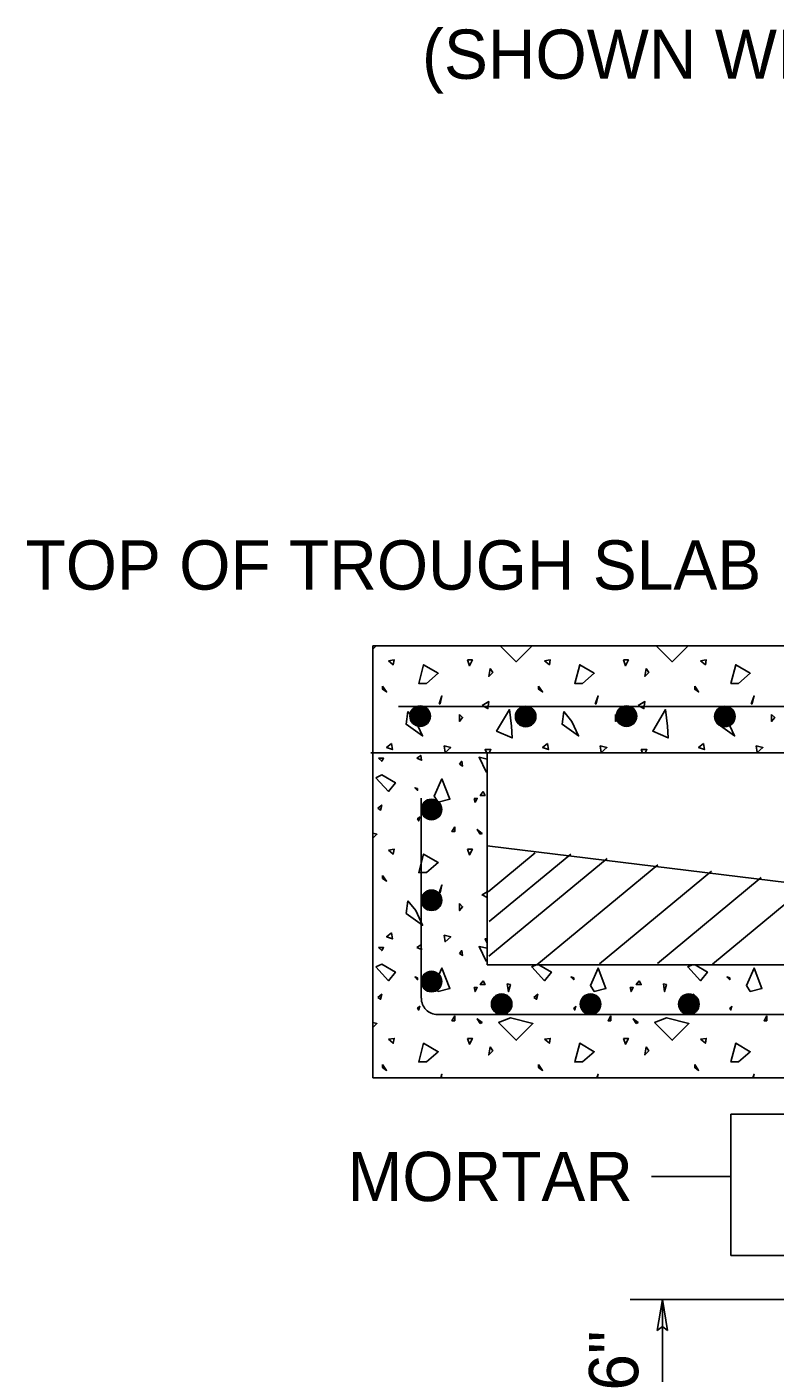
# Model space of a CAD drawing. Extents: x 5.8 to 18, y -5.2 to 5.4.
# Drawn here: x 5.844 to 6.755, y -0.7 to 0.939 of the extents above; entities that cross this region are included whole.
import ezdxf

# ---------------------------------------------------------------- set-up
doc = ezdxf.new("R2010")
doc.units = 0
for name, color, linetype in [('DETL-DIMS', 7, 'Continuous'), ('DETL-LINE', 7, 'Continuous'), ('DETL-NOTE', 7, 'Continuous'), ('DETL-PATT', 7, 'Continuous')]:
    doc.layers.add(name, color=color, linetype=linetype)

msp = doc.modelspace()

# ---------------------------------------------------------------- linework, layer by layer
at = {"layer": 'DETL-DIMS'}
for p, q in [((6.7009, -0.4604), (6.7009, -0.3844)), ((6.7009, -0.3844), (7.037, -0.3844)), ((6.6043, -0.4604), (6.7009, -0.4604)), ((6.7009, -0.4604), (6.7009, -0.5566)), ((6.7009, -0.5566), (7.0309, -0.5566)), ((6.8399, -0.6101), (6.5782, -0.6101)), ((6.6112, -0.6478), (6.6175, -0.6101)), ((6.6175, -0.7393), (6.6175, -0.6101)), ((6.6237, -0.6478), (6.6175, -0.6101)), ((6.6112, -0.6478), (6.6175, -0.6431)), ((6.6237, -0.6478), (6.6175, -0.6431))]:
    msp.add_line(p, q, dxfattribs=at)
at = {"layer": 'DETL-LINE'}
for p, q in [((6.2649, -0.3403), (6.2649, 0.1856)), ((6.2649, 0.1856), (8.658, 0.1856)), ((6.296, 0.112), (7.1107, 0.112)), ((6.2624, 0.0554), (8.658, 0.0554)), ((6.404, -0.2028), (6.404, 0.0554)), ((6.3238, -0.2434), (6.3238, 0.0002)), ((7.1567, -0.1499), (6.404, -0.0577)), ((6.404, -0.2028), (8.5262, -0.2028)), ((6.3435, -0.2631), (7.0378, -0.2631)), ((6.2649, -0.3403), (7.037, -0.3403))]:
    msp.add_line(p, q, dxfattribs=at)
for centre, radius in [((6.3224, 0.1001), 0.0125), ((6.3223, 0.1002), 0.0116), ((6.3212, 0.1002), 0.0101), ((6.3224, 0.0999), 0.0112), ((6.3228, 0.0993), 0.011), ((6.3227, 0.0997), 0.0102), ((6.3216, 0.1007), 0.00834), ((6.323, 0.0997), 0.00969), ((6.3231, 0.0994), 0.00918), ((6.3214, 0.0997), 0.00724), ((6.3232, 0.0993), 0.00876), ((6.3231, 0.0991), 0.00835), ((6.3208, 0.0993), 0.00578), ((6.3233, 0.0991), 0.00814), ((6.3231, 0.0992), 0.00786), ((6.3235, 0.099), 0.00751), ((6.3235, 0.0991), 0.00704), ((6.3236, 0.0992), 0.00655), ((6.3217, 0.0995), 0.00467), ((6.3236, 0.0993), 0.006), ((6.3237, 0.0992), 0.00565), ((6.3237, 0.0991), 0.0051), ((6.3239, 0.0987), 0.00488), ((6.324, 0.0986), 0.00445), ((6.324, 0.0988), 0.0039), ((6.3242, 0.0989), 0.00377), ((6.3242, 0.0985), 0.00347), ((6.3243, 0.0988), 0.00333), ((6.3244, 0.0987), 0.00285), ((6.3242, 0.0989), 0.00238), ((6.3245, 0.0986), 0.00212), ((6.3245, 0.0986), 0.00175), ((6.3247, 0.0986), 0.00133), ((6.3247, 0.0987), 0.00118), ((6.3251, 0.0986), 0.00148), ((6.3246, 0.0987), 0.000769), ((6.3245, 0.0987), 0.000362), ((6.3248, 0.0987), 0.00023), ((6.451, 0.0996), 0.0125), ((6.4509, 0.0997), 0.0116), ((6.4498, 0.0997), 0.0101), ((6.451, 0.0994), 0.0112), ((6.4513, 0.0988), 0.011), ((6.4513, 0.0992), 0.0102), ((6.4502, 0.1002), 0.00834), ((6.4516, 0.0992), 0.00969), ((6.4516, 0.0989), 0.00918), ((6.45, 0.0992), 0.00724), ((6.4518, 0.0988), 0.00876), ((6.4516, 0.0986), 0.00835), ((6.4493, 0.0988), 0.00578), ((6.4519, 0.0986), 0.00814), ((6.4517, 0.0987), 0.00786), ((6.4521, 0.0985), 0.00751), ((6.4521, 0.0986), 0.00704), ((6.4522, 0.0987), 0.00655), ((6.4503, 0.099), 0.00467), ((6.4522, 0.0988), 0.006), ((6.4523, 0.0987), 0.00565), ((6.4523, 0.0986), 0.0051), ((6.4525, 0.0982), 0.00488), ((6.4526, 0.0981), 0.00445), ((6.4526, 0.0983), 0.0039), ((6.4528, 0.0984), 0.00377), ((6.4528, 0.098), 0.00347), ((6.4529, 0.0983), 0.00333), ((6.453, 0.0982), 0.00285), ((6.4528, 0.0984), 0.00238), ((6.453, 0.0981), 0.00212), ((6.4531, 0.0981), 0.00175), ((6.4532, 0.0981), 0.00133), ((6.4532, 0.0982), 0.00118), ((6.4537, 0.0981), 0.00148), ((6.4532, 0.0982), 0.000769), ((6.4531, 0.0982), 0.000362), ((6.4534, 0.0982), 0.00023), ((6.5737, 0.1001), 0.0125), ((6.5736, 0.1002), 0.0116), ((6.5725, 0.1002), 0.0101), ((6.5738, 0.0999), 0.0112), ((6.5741, 0.0993), 0.011), ((6.574, 0.0997), 0.0102), ((6.5743, 0.0997), 0.00969), ((6.5729, 0.1007), 0.00834), ((6.5744, 0.0994), 0.00918), ((6.5727, 0.0997), 0.00724), ((6.5745, 0.0993), 0.00876), ((6.5744, 0.0991), 0.00835), ((6.5721, 0.0993), 0.00578), ((6.5746, 0.0991), 0.00814), ((6.5745, 0.0992), 0.00786), ((6.5748, 0.099), 0.00751), ((6.5749, 0.0991), 0.00704), ((6.5749, 0.0992), 0.00655), ((6.5731, 0.0995), 0.00467), ((6.5749, 0.0993), 0.006), ((6.575, 0.0992), 0.00565), ((6.575, 0.0991), 0.0051), ((6.5752, 0.0987), 0.00488), ((6.5754, 0.0986), 0.00445), ((6.5754, 0.0988), 0.0039), ((6.5755, 0.0989), 0.00377), ((6.5755, 0.0985), 0.00347), ((6.5756, 0.0988), 0.00333), ((6.5757, 0.0987), 0.00285), ((6.5755, 0.0989), 0.00238), ((6.5758, 0.0986), 0.00212), ((6.5759, 0.0986), 0.00175), ((6.576, 0.0986), 0.00133), ((6.576, 0.0987), 0.00118), ((6.5764, 0.0986), 0.00148), ((6.576, 0.0987), 0.000769), ((6.5758, 0.0987), 0.000362), ((6.5761, 0.0987), 0.00023), ((6.6935, 0.0996), 0.0125), ((6.6934, 0.0997), 0.0116), ((6.6923, 0.0997), 0.0101), ((6.6936, 0.0994), 0.0112), ((6.6939, 0.0988), 0.011), ((6.6938, 0.0992), 0.0102), ((6.6941, 0.0992), 0.00969), ((6.6927, 0.1002), 0.00834), ((6.6942, 0.0989), 0.00918), ((6.6925, 0.0992), 0.00724), ((6.6943, 0.0988), 0.00876), ((6.6942, 0.0986), 0.00835), ((6.6919, 0.0988), 0.00578), ((6.6944, 0.0986), 0.00814), ((6.6942, 0.0987), 0.00786), ((6.6946, 0.0985), 0.00751), ((6.6947, 0.0986), 0.00704), ((6.6947, 0.0987), 0.00655), ((6.6929, 0.099), 0.00467), ((6.6947, 0.0988), 0.006), ((6.6948, 0.0987), 0.00565), ((6.6948, 0.0986), 0.0051), ((6.695, 0.0982), 0.00488), ((6.6951, 0.0981), 0.00445), ((6.6951, 0.0983), 0.0039), ((6.6953, 0.0984), 0.00377), ((6.6953, 0.098), 0.00347), ((6.6954, 0.0983), 0.00333), ((6.6955, 0.0982), 0.00285), ((6.6953, 0.0984), 0.00238), ((6.6956, 0.0981), 0.00212), ((6.6957, 0.0981), 0.00175), ((6.6958, 0.0981), 0.00133), ((6.6958, 0.0982), 0.00118), ((6.6962, 0.0981), 0.00148), ((6.6958, 0.0982), 0.000769), ((6.6956, 0.0982), 0.000362), ((6.6959, 0.0982), 0.00023), ((6.3363, -0.0135), 0.0125), ((6.3362, -0.0134), 0.0116), ((6.3351, -0.0134), 0.0101), ((6.3363, -0.0136), 0.0112), ((6.3367, -0.0142), 0.011), ((6.3366, -0.0138), 0.0102), ((6.3369, -0.0138), 0.00969), ((6.3355, -0.0129), 0.00834), ((6.337, -0.0141), 0.00918), ((6.3353, -0.0138), 0.00724), ((6.3371, -0.0143), 0.00876), ((6.337, -0.0145), 0.00835), ((6.3347, -0.0143), 0.00578), ((6.3372, -0.0145), 0.00814), ((6.337, -0.0143), 0.00786), ((6.3374, -0.0145), 0.00751), ((6.3375, -0.0144), 0.00704), ((6.3375, -0.0143), 0.00655), ((6.3356, -0.014), 0.00467), ((6.3375, -0.0142), 0.006), ((6.3376, -0.0143), 0.00565), ((6.3376, -0.0144), 0.0051), ((6.3378, -0.0148), 0.00488), ((6.3379, -0.0149), 0.00445), ((6.3379, -0.0148), 0.0039), ((6.3381, -0.0147), 0.00377), ((6.3381, -0.015), 0.00347), ((6.3382, -0.0147), 0.00333), ((6.3383, -0.0148), 0.00285), ((6.3381, -0.0146), 0.00238), ((6.3384, -0.0149), 0.00212), ((6.3384, -0.0149), 0.00175), ((6.3386, -0.015), 0.00133), ((6.3386, -0.0148), 0.00118), ((6.339, -0.0149), 0.00148), ((6.3386, -0.0148), 0.000769), ((6.3384, -0.0148), 0.000362), ((6.3387, -0.0148), 0.00023), ((6.3363, -0.1241), 0.0125), ((6.3362, -0.124), 0.0116), ((6.3351, -0.124), 0.0101), ((6.3363, -0.1243), 0.0112), ((6.3367, -0.1248), 0.011), ((6.3366, -0.1244), 0.0102), ((6.3369, -0.1245), 0.00969), ((6.3355, -0.1235), 0.00834), ((6.337, -0.1248), 0.00918), ((6.3353, -0.1245), 0.00724), ((6.3371, -0.1249), 0.00876), ((6.337, -0.1251), 0.00835), ((6.3347, -0.1249), 0.00578), ((6.3372, -0.1251), 0.00814), ((6.337, -0.125), 0.00786), ((6.3374, -0.1252), 0.00751), ((6.3375, -0.1251), 0.00704), ((6.3375, -0.125), 0.00655), ((6.3356, -0.1246), 0.00467), ((6.3375, -0.1248), 0.006), ((6.3376, -0.125), 0.00565), ((6.3376, -0.1251), 0.0051), ((6.3378, -0.1255), 0.00488), ((6.3379, -0.1255), 0.00445), ((6.3379, -0.1254), 0.0039), ((6.3381, -0.1253), 0.00377), ((6.3381, -0.1257), 0.00347), ((6.3382, -0.1254), 0.00333), ((6.3383, -0.1255), 0.00285), ((6.3381, -0.1253), 0.00238), ((6.3384, -0.1256), 0.00212), ((6.3384, -0.1255), 0.00175), ((6.3386, -0.1256), 0.00133), ((6.3386, -0.1255), 0.00118), ((6.339, -0.1255), 0.00148), ((6.3386, -0.1255), 0.000769), ((6.3384, -0.1255), 0.000362), ((6.3387, -0.1255), 0.00023), ((6.3363, -0.2231), 0.0125), ((6.3362, -0.223), 0.0116), ((6.3351, -0.223), 0.0101), ((6.3363, -0.2233), 0.0112), ((6.3367, -0.2238), 0.011), ((6.3366, -0.2234), 0.0102), ((6.3369, -0.2235), 0.00969), ((6.3355, -0.2225), 0.00834), ((6.337, -0.2238), 0.00918), ((6.3353, -0.2235), 0.00724), ((6.3371, -0.2239), 0.00876), ((6.337, -0.2241), 0.00835), ((6.3347, -0.2239), 0.00578), ((6.3372, -0.2241), 0.00814), ((6.337, -0.224), 0.00786), ((6.3374, -0.2242), 0.00751), ((6.3375, -0.224), 0.00704), ((6.3375, -0.224), 0.00655), ((6.3356, -0.2236), 0.00467), ((6.3375, -0.2238), 0.006), ((6.3376, -0.224), 0.00565), ((6.3376, -0.224), 0.0051), ((6.3378, -0.2245), 0.00488), ((6.3379, -0.2245), 0.00445), ((6.3379, -0.2244), 0.0039), ((6.3381, -0.2243), 0.00377), ((6.3381, -0.2247), 0.00347), ((6.3382, -0.2244), 0.00333), ((6.3383, -0.2245), 0.00285), ((6.3381, -0.2243), 0.00238), ((6.3384, -0.2245), 0.00212), ((6.3384, -0.2245), 0.00175), ((6.3386, -0.2246), 0.00133), ((6.3386, -0.2245), 0.00118), ((6.339, -0.2245), 0.00148), ((6.3386, -0.2245), 0.000769), ((6.3384, -0.2245), 0.000362), ((6.3387, -0.2245), 0.00023), ((6.4217, -0.2506), 0.0125), ((6.4216, -0.2505), 0.0116), ((6.4205, -0.2505), 0.0101), ((6.4218, -0.2508), 0.0112), ((6.4221, -0.2514), 0.011), ((6.422, -0.251), 0.0102), ((6.4223, -0.251), 0.00969), ((6.4209, -0.25), 0.00834), ((6.4224, -0.2513), 0.00918), ((6.4207, -0.251), 0.00724), ((6.4225, -0.2514), 0.00876), ((6.4224, -0.2516), 0.00835), ((6.4201, -0.2514), 0.00578), ((6.4226, -0.2516), 0.00814), ((6.4224, -0.2515), 0.00786), ((6.4228, -0.2517), 0.00751), ((6.4229, -0.2516), 0.00704), ((6.4229, -0.2515), 0.00655), ((6.4229, -0.2514), 0.006), ((6.5299, -0.2506), 0.0125), ((6.5298, -0.2505), 0.0116), ((6.5287, -0.2505), 0.0101), ((6.5299, -0.2508), 0.0112), ((6.5302, -0.2514), 0.011), ((6.5302, -0.251), 0.0102), ((6.5291, -0.25), 0.00834), ((6.5305, -0.251), 0.00969), ((6.5305, -0.2513), 0.00918), ((6.5289, -0.251), 0.00724), ((6.5307, -0.2514), 0.00876), ((6.5305, -0.2516), 0.00835), ((6.5282, -0.2514), 0.00578), ((6.5308, -0.2516), 0.00814), ((6.5306, -0.2515), 0.00786), ((6.531, -0.2517), 0.00751), ((6.531, -0.2516), 0.00704), ((6.5311, -0.2515), 0.00655), ((6.5311, -0.2514), 0.006), ((6.6497, -0.2506), 0.0125), ((6.6496, -0.2505), 0.0116), ((6.6485, -0.2505), 0.0101), ((6.6497, -0.2508), 0.0112), ((6.6501, -0.2514), 0.011), ((6.65, -0.251), 0.0102), ((6.6489, -0.25), 0.00834), ((6.6503, -0.251), 0.00969), ((6.6503, -0.2513), 0.00918), ((6.6487, -0.251), 0.00724), ((6.6505, -0.2514), 0.00876), ((6.6503, -0.2516), 0.00835), ((6.6481, -0.2514), 0.00578), ((6.6506, -0.2516), 0.00814), ((6.6504, -0.2515), 0.00786), ((6.6508, -0.2517), 0.00751), ((6.6508, -0.2516), 0.00704), ((6.6509, -0.2515), 0.00655), ((6.6509, -0.2514), 0.006), ((6.4211, -0.2512), 0.00467), ((6.423, -0.2515), 0.00565), ((6.423, -0.2516), 0.0051), ((6.4232, -0.252), 0.00488), ((6.4233, -0.2521), 0.00445), ((6.4233, -0.2519), 0.0039), ((6.4235, -0.2518), 0.00377), ((6.4235, -0.2522), 0.00347), ((6.4236, -0.2519), 0.00333), ((6.4237, -0.252), 0.00285), ((6.4235, -0.2518), 0.00238), ((6.4238, -0.2521), 0.00212), ((6.4239, -0.2521), 0.00175), ((6.424, -0.2521), 0.00133), ((6.424, -0.252), 0.00118), ((6.4244, -0.2521), 0.00148), ((6.424, -0.252), 0.000769), ((6.4238, -0.252), 0.000362), ((6.4241, -0.252), 0.00023), ((6.5292, -0.2512), 0.00467), ((6.5312, -0.2515), 0.00565), ((6.5312, -0.2516), 0.0051), ((6.5314, -0.252), 0.00488), ((6.5315, -0.2521), 0.00445), ((6.5315, -0.2519), 0.0039), ((6.5317, -0.2518), 0.00377), ((6.5317, -0.2522), 0.00347), ((6.5318, -0.2519), 0.00333), ((6.5319, -0.252), 0.00285), ((6.5317, -0.2518), 0.00238), ((6.5319, -0.2521), 0.00212), ((6.532, -0.2521), 0.00175), ((6.5321, -0.2521), 0.00133), ((6.5321, -0.252), 0.00118), ((6.5326, -0.2521), 0.00148), ((6.5321, -0.252), 0.000769), ((6.532, -0.252), 0.000362), ((6.5323, -0.252), 0.00023), ((6.649, -0.2512), 0.00467), ((6.651, -0.2515), 0.00565), ((6.651, -0.2516), 0.0051), ((6.6512, -0.252), 0.00488), ((6.6513, -0.2521), 0.00445), ((6.6513, -0.2519), 0.0039), ((6.6515, -0.2518), 0.00377), ((6.6515, -0.2522), 0.00347), ((6.6516, -0.2519), 0.00333), ((6.6517, -0.252), 0.00285), ((6.6515, -0.2518), 0.00238), ((6.6517, -0.2521), 0.00212), ((6.6518, -0.2521), 0.00175), ((6.652, -0.2521), 0.00133), ((6.652, -0.252), 0.00118), ((6.6524, -0.2521), 0.00148), ((6.6519, -0.252), 0.000769), ((6.6518, -0.252), 0.000362), ((6.6521, -0.252), 0.00023)]:
    msp.add_circle(centre, radius, dxfattribs=at)
msp.add_arc((6.3435, -0.2435), 0.0196, 179.6246, 270, dxfattribs=at)
at = {"layer": 'DETL-PATT'}
for p, q in [((6.4053, -0.1137), (6.4625, -0.0663)), ((6.4062, -0.1922), (6.5501, -0.0732)), ((6.4065, -0.1499), (6.5058, -0.0678)), ((6.4644, -0.2029), (6.612, -0.0808)), ((6.541, -0.2014), (6.6771, -0.0888)), ((6.6114, -0.2009), (6.7379, -0.0962)), ((6.6786, -0.2017), (6.7973, -0.1035))]:
    msp.add_line(p, q, dxfattribs=at)
for points in [[(6.2687, 0.1856), (6.2649, 0.1818)], [(6.4587, 0.1856), (6.4394, 0.1663), (6.42, 0.1856)], [(6.6488, 0.1856), (6.6294, 0.1663), (6.61, 0.1856)], [(6.404, 0.0478), (6.3942, 0.05), (6.4027, 0.0322), (6.404, 0.0334)], [(6.4066, 0.0554), (6.4086, 0.0593), (6.4015, 0.0593), (6.404, 0.0542)], [(6.5966, 0.0554), (6.5986, 0.0593), (6.5916, 0.0593), (6.5934, 0.0554)], [(6.2649, -0.0426), (6.2697, -0.0438), (6.2649, -0.0486)], [(6.404, -0.1139), (6.3979, -0.1175), (6.404, -0.1207)], [(6.404, -0.1711), (6.4015, -0.1711), (6.404, -0.1763)], [(6.404, -0.1826), (6.3942, -0.1805), (6.4027, -0.1982), (6.404, -0.197)], [(6.4638, -0.2028), (6.4583, -0.2053), (6.4738, -0.222), (6.4823, -0.2115), (6.4671, -0.2028)], [(6.6538, -0.2028), (6.6483, -0.2053), (6.6638, -0.222), (6.6723, -0.2115), (6.6572, -0.2028)], [(6.2649, -0.2729), (6.2697, -0.2742), (6.2649, -0.279)], [(6.348, -0.3403), (6.349, -0.336), (6.3475, -0.3403)], [(6.538, -0.3403), (6.5391, -0.336), (6.5376, -0.3403)], [(6.7281, -0.3403), (6.7291, -0.336), (6.7276, -0.3403)]]:
    msp.add_lwpolyline(points, dxfattribs=at)
for points in [[(6.2838, 0.1674), (6.2897, 0.1626), (6.2909, 0.1685)], [(6.3801, 0.1685), (6.3824, 0.1615), (6.386, 0.1685)], [(6.4738, 0.1674), (6.4798, 0.1626), (6.4809, 0.1685)], [(6.5701, 0.1685), (6.5724, 0.1615), (6.576, 0.1685)], [(6.6638, 0.1674), (6.6698, 0.1626), (6.6709, 0.1685)], [(6.3301, 0.14), (6.3445, 0.1522), (6.3267, 0.1626), (6.3208, 0.14)], [(6.4075, 0.1581), (6.406, 0.1485), (6.4109, 0.1533)], [(6.5201, 0.14), (6.5345, 0.1522), (6.5167, 0.1626), (6.5108, 0.14)], [(6.5975, 0.1581), (6.5961, 0.1485), (6.6009, 0.1533)], [(6.7102, 0.14), (6.7245, 0.1522), (6.7067, 0.1626), (6.7008, 0.14)], [(6.2767, 0.1366), (6.2767, 0.1329), (6.2815, 0.1296)], [(6.4667, 0.1366), (6.4667, 0.1329), (6.4716, 0.1296)], [(6.6568, 0.1366), (6.6568, 0.1329), (6.6616, 0.1296)], [(6.3456, 0.1152), (6.3467, 0.1152), (6.349, 0.1248)], [(6.3979, 0.1129), (6.4049, 0.1093), (6.406, 0.1177)], [(6.5356, 0.1152), (6.5368, 0.1152), (6.5391, 0.1248)], [(6.5879, 0.1129), (6.5949, 0.1093), (6.5961, 0.1177)], [(6.7257, 0.1152), (6.7268, 0.1152), (6.7291, 0.1248)], [(6.3075, 0.1056), (6.3053, 0.0903), (6.3253, 0.0759), (6.3171, 0.0937)], [(6.3705, 0.1022), (6.3705, 0.0937), (6.3742, 0.0985)], [(6.4335, 0.0878), (6.4346, 0.0736), (6.4156, 0.0818), (6.4312, 0.1081)], [(6.4975, 0.1056), (6.4953, 0.0903), (6.5153, 0.0759), (6.5071, 0.0937)], [(6.5605, 0.1022), (6.5605, 0.0937), (6.5642, 0.0985)], [(6.6235, 0.0878), (6.6246, 0.0736), (6.6057, 0.0818), (6.6212, 0.1081)], [(6.6876, 0.1056), (6.6853, 0.0903), (6.7053, 0.0759), (6.6972, 0.0937)], [(6.7505, 0.1022), (6.7505, 0.0937), (6.7542, 0.0985)], [(6.2875, 0.0666), (6.2815, 0.0618), (6.2886, 0.0593)], [(6.4775, 0.0666), (6.4716, 0.0618), (6.4786, 0.0593)], [(6.6675, 0.0666), (6.6616, 0.0618), (6.6686, 0.0593)], [(6.3182, 0.0488), (6.3242, 0.0463), (6.3231, 0.0522)], [(6.3516, 0.0641), (6.3527, 0.0559), (6.3598, 0.0618)], [(6.5416, 0.0641), (6.5427, 0.0559), (6.5498, 0.0618)], [(6.7316, 0.0641), (6.7327, 0.0559), (6.7398, 0.0618)], [(6.2719, 0.0488), (6.2756, 0.0451), (6.2779, 0.0488)], [(6.3705, 0.0415), (6.3742, 0.0392), (6.373, 0.0451)], [(6.2683, 0.0251), (6.2838, 0.0084), (6.2923, 0.0189), (6.2756, 0.0285)], [(6.3445, -0.0048), (6.3586, -0.0012), (6.349, 0.0237), (6.3397, 0.0025)], [(6.3194, 0.0118), (6.316, 0.0129), (6.3194, 0.0096)], [(6.399, 0.0084), (6.4015, 0.0036), (6.3956, 0.0036)], [(6.2708, -0.0119), (6.2742, -0.0142), (6.2756, -0.0082)], [(6.3883, 0), (6.3894, -0.0048), (6.3919, 0)], [(6.3219, -0.0226), (6.3194, -0.0249), (6.3208, -0.0274)], [(6.3645, -0.0345), (6.3612, -0.0404), (6.3645, -0.0404)], [(6.3956, -0.0438), (6.3979, -0.0427), (6.3919, -0.0379)], [(6.2838, -0.063), (6.2897, -0.0678), (6.2909, -0.0619)], [(6.3801, -0.0619), (6.3824, -0.0689), (6.386, -0.0619)], [(6.3301, -0.0904), (6.3445, -0.0782), (6.3267, -0.0678), (6.3208, -0.0904)], [(6.2767, -0.0938), (6.2767, -0.0975), (6.2815, -0.1008)], [(6.3456, -0.1152), (6.3467, -0.1152), (6.349, -0.1057)], [(6.3075, -0.1248), (6.3053, -0.1401), (6.3253, -0.1545), (6.3171, -0.1367)], [(6.3705, -0.1282), (6.3705, -0.1367), (6.3742, -0.1319)], [(6.2875, -0.1638), (6.2815, -0.1686), (6.2886, -0.1711)], [(6.3182, -0.1816), (6.3242, -0.1841), (6.3231, -0.1782)], [(6.3516, -0.1664), (6.3527, -0.1745), (6.3598, -0.1686)], [(6.2719, -0.1816), (6.2756, -0.1853), (6.2779, -0.1816)], [(6.3705, -0.1889), (6.3742, -0.1912), (6.373, -0.1853)], [(6.2683, -0.2053), (6.2838, -0.222), (6.2923, -0.2115), (6.2756, -0.2019)], [(6.3445, -0.2352), (6.3586, -0.2316), (6.349, -0.2067), (6.3397, -0.2279)], [(6.5345, -0.2352), (6.5486, -0.2316), (6.5391, -0.2067), (6.5297, -0.2279)], [(6.7245, -0.2352), (6.7387, -0.2316), (6.7291, -0.2067), (6.7198, -0.2279)], [(6.3194, -0.2186), (6.316, -0.2175), (6.3194, -0.2208)], [(6.399, -0.222), (6.4015, -0.2267), (6.3956, -0.2267)], [(6.4286, -0.2257), (6.43, -0.2352), (6.4323, -0.2267)], [(6.5094, -0.2186), (6.506, -0.2175), (6.5094, -0.2208)], [(6.589, -0.222), (6.5916, -0.2267), (6.5856, -0.2267)], [(6.6187, -0.2257), (6.6201, -0.2352), (6.6224, -0.2267)], [(6.6994, -0.2186), (6.696, -0.2175), (6.6994, -0.2208)], [(6.2708, -0.2423), (6.2742, -0.2446), (6.2756, -0.2386)], [(6.3883, -0.2304), (6.3894, -0.2352), (6.3919, -0.2304)], [(6.4608, -0.2423), (6.4642, -0.2446), (6.4656, -0.2386)], [(6.5783, -0.2304), (6.5794, -0.2352), (6.582, -0.2304)], [(6.6509, -0.2423), (6.6542, -0.2446), (6.6556, -0.2386)], [(6.3219, -0.253), (6.3194, -0.2553), (6.3208, -0.2578)], [(6.5119, -0.253), (6.5094, -0.2553), (6.5108, -0.2578)], [(6.702, -0.253), (6.6994, -0.2553), (6.7008, -0.2578)], [(6.3645, -0.2649), (6.3612, -0.2708), (6.3645, -0.2708)], [(6.3956, -0.2742), (6.3979, -0.2731), (6.3919, -0.2683)], [(6.4323, -0.2671), (6.4597, -0.2742), (6.4394, -0.2945), (6.4179, -0.2731)], [(6.5546, -0.2649), (6.5512, -0.2708), (6.5546, -0.2708)], [(6.5856, -0.2742), (6.5879, -0.2731), (6.582, -0.2683)], [(6.6224, -0.2671), (6.6497, -0.2742), (6.6294, -0.2945), (6.6079, -0.2731)], [(6.7446, -0.2649), (6.7412, -0.2708), (6.7446, -0.2708)], [(6.2838, -0.2934), (6.2897, -0.2982), (6.2909, -0.2923)], [(6.3801, -0.2923), (6.3824, -0.2993), (6.386, -0.2923)], [(6.4738, -0.2934), (6.4798, -0.2982), (6.4809, -0.2923)], [(6.5701, -0.2923), (6.5724, -0.2993), (6.576, -0.2923)], [(6.6638, -0.2934), (6.6698, -0.2982), (6.6709, -0.2923)], [(6.3301, -0.3208), (6.3445, -0.3086), (6.3267, -0.2982), (6.3208, -0.3208)], [(6.4075, -0.3027), (6.406, -0.3123), (6.4109, -0.3075)], [(6.5201, -0.3208), (6.5345, -0.3086), (6.5167, -0.2982), (6.5108, -0.3208)], [(6.5975, -0.3027), (6.5961, -0.3123), (6.6009, -0.3075)], [(6.7102, -0.3208), (6.7245, -0.3086), (6.7067, -0.2982), (6.7008, -0.3208)], [(6.2767, -0.3242), (6.2767, -0.3278), (6.2815, -0.3312)], [(6.4667, -0.3242), (6.4667, -0.3278), (6.4716, -0.3312)], [(6.6568, -0.3242), (6.6568, -0.3278), (6.6616, -0.3312)]]:
    msp.add_lwpolyline(points, close=True, dxfattribs=at)

# ---------------------------------------------------------------- texts
at = {"layer": 'DETL-NOTE'}
for s, p in [('(SHOWN WITHOUT TROUGH SLAB)', (6.3247, 0.876)), ('TOP OF TROUGH SLAB', (5.8418, 0.2541)), ('MORTAR', (6.2339, -0.4904))]:
    msp.add_text(s, height=0.06, dxfattribs=at).set_placement(p)
msp.add_text('6"', height=0.06, rotation=90, dxfattribs=at).set_placement((6.588, -0.7211))

doc.saveas('drawing.dxf')
